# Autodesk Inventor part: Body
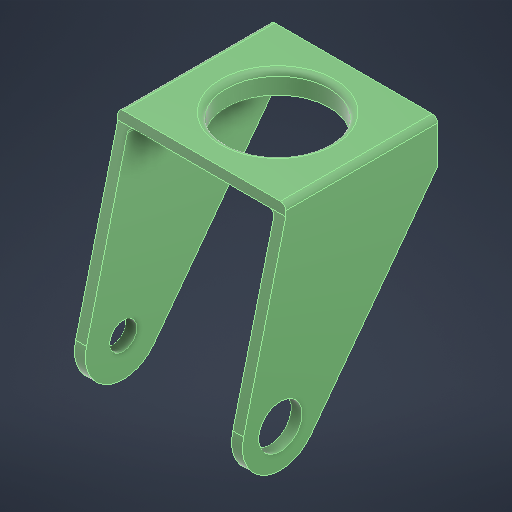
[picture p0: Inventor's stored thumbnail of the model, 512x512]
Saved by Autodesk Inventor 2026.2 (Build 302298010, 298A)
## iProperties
Created: 2021-06
Part Number: Body
Material: Generic
Document SubType Name: Modeling
Designer: ASUS
Density: 1 g/cm^3
Appearance: Smooth - Dark Forest Green
Author: ASUS
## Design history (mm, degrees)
sketch "Sketch1"
  geometry: L1 (15.5, 14)-(-15.5, 14); L2 (-15.5, 14)-(-15.5, -14); L3 (-15.5, -14)-(15.5, -14); L4 (15.5, -14)-(15.5, 14); L5 (15.5, 14)-(-15.5, -14); L6 (-15.5, 14)-(15.5, -14); 1 further point
  constraints: 12 end point, 2 midpoint, 2 parallel, 1 horizontal, 1 perpendicular
  dimensions: "d0" = 31 distance of L3.end L2.end; "d1" = 28 distance of L2.end L1.end
extrude "Extrusion1" new body sketch "Sketch1" distance "d2" = 2; taper "d3" = 0 deg
sketch "Sketch2"
  geometry: L1 (28, -2)-(0, -2) reference; L2 (28, -2)-(28, -8); L3 (0, 0)-(28, 0) reference; L4 (28, -8)-(4.6, -39.2); L5 (0, -2)-(-7.793, -33.309); A1 r 7 centre (-1, -35) between (4.6, -39.2) and (-7.793, -33.309); 1 further point
  constraints: 6 end point, 2 point on circle, 2 tangent, 1 centre point, 1 vertical
  dimensions: "d4" = 14 diameter of A1; "d5" = 35 vertical distance of point (14, 0) A1.centre; "d6" = 15 horizontal distance of point (14, 0) A1.centre; "d7" = 8 distance from line of L3 L2.end
extrude "Extrusion2" join sketch "Sketch2" distance "d8" = 2; taper "d9" = 0 deg
mirror "Mirror1"
sketch "Sketch3"
  geometry: A1 r 7 centre (-1, -35) between (-7.793, -33.309) and (4.6, -39.2) reference; 2 further points
  constraints: 1 coincident
hole "Hole1" sketch "Sketch3" diameter "d10" = 8; stored, may be unused: countersink angle "d14" = 90 deg, drill point angle "d16" = 0 deg; dims "d11" = 8, "d12" = 4, "d13" = 2, "d15" = 11.8
sketch "Sketch4"
  geometry: A1 r 7 centre (-29, -27) between (-35.793, -25.309) and (-23.4, -31.2) reference; 2 further points
  constraints: 1 coincident
hole "Hole2" sketch "Sketch4" diameter "d17" = 5; stored, may be unused: countersink angle "d21" = 90 deg, drill point angle "d23" = 0 deg; dims "d18" = 8, "d19" = 4, "d20" = 2, "d22" = 11.8
sketch "Sketch5"
  geometry: C1 r 11.5 at (0, 0); 1 further point
  constraints: 1 centre point, 1 coincident
  dimensions: "d24" = 23 diameter of C1
extrude "Extrusion3" join sketch "Sketch5" distance "d25" = 4; taper "d26" = 0 deg
sketch "Sketch6"
  geometry: C1 r 11.5 at (0, 0) reference; 2 further points
  constraints: 1 coincident
hole "Hole3" sketch "Sketch6" diameter "d27" = 19; stored, may be unused: countersink angle "d31" = 90 deg, drill point angle "d33" = 0 deg; dims "d28" = 8, "d29" = 4, "d30" = 2, "d32" = 11.8
fillet "Fillet1" dims "d34" = 1
body "Solid1"
